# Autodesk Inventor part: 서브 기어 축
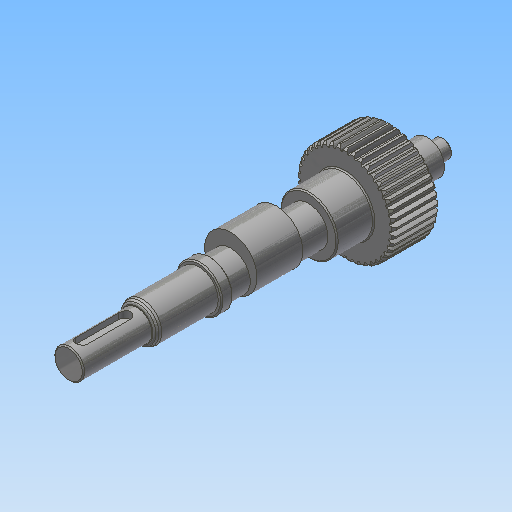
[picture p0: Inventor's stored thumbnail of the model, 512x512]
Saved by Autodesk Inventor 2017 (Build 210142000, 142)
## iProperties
Created: 2018-12
Part Number: 서브 기어 축
Material: 강철, 연강
Document SubType Name: Modeling
Designer: mduedu
Categories: <?xml version="1.0" encoding="UTF-16"?> <MemberInstance><Categories><FamilyTemplate><FamilyTemplateParameter ValueType="xs:double" Id="1" ObjectReferenceKey="da
Density: 7.86 g/cm^3
Appearance: 강철
Mass: 488.187 g
Surface Area: 153.344 cm^2
Volume: 62.1103 cm^3
Author: mduedu
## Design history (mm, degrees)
sketch "Sketch1"
  geometry: C1 r 21.3 at (0, 0)
  constraints: 1 centre point
  dimensions: "d0" = 42.6 diameter of C1 (= da_da)
extrude "Extrusion1" new body sketch "Sketch1" distance "d1" = 20 (= da_b); taper "d2" = 0 deg
workplane "Work Plane2"
sketch "Sketch2"
  geometry: C1 r 21.3 at (0, 0) reference; C2 r 20.5 at (0, 0)
  constraints: 1 centre point, 1 coincident
  dimensions: "d3" = 41 diameter of C2 (= da_dw)
feature "피치 지름" sketch "Sketch2" dims "d4" = 10, "d5" = 0
workplane "Work Plane8"
workplane "Work Plane9"
chamfer "모따기1" distance "d49" = 1; stored, may be unused: second distance "d50" = 2, angle "d51" = 45 deg
sketch "스케치3"
  geometry: C1 r 12.5 at (0, 0); 1 further point
  constraints: 1 centre point, 1 coincident
  dimensions: "d52" = 25 diameter of C1
extrude "돌출2" join sketch "스케치3" distance "d53" = 16; taper "d54" = 0 deg
sketch "스케치4"
  geometry: C1 r 8.5 at (0, 0); 1 further point
  constraints: 1 centre point, 1 coincident
  dimensions: "d55" = 17 diameter of C1
extrude "돌출3" join sketch "스케치4" distance "d56" = 105; taper "d57" = 0 deg
sketch "스케치5"
  geometry: C1 r 7.5 at (0, 0); 1 further point
  constraints: 1 centre point, 1 coincident
  dimensions: "d58" = 15 diameter of C1
extrude "돌출4" join sketch "스케치5" distance "d59" = 16; taper "d60" = 0 deg
sketch "스케치6"
  geometry: C1 r 4 at (0, 0); 1 further point
  constraints: 1 centre point, 1 coincident
  dimensions: "d61" = 8 diameter of C1
extrude "돌출5" join sketch "스케치6" distance "d62" = 7; taper "d63" = 0 deg
fillet "모깎기1" dims "d67" = 0.5
feature "스퍼 기어" dims "da_b" = 20, "da_d" = 41, "da_aw" = 31, "da_da" = 42.6, "da_df" = 39.086, "da_dw" = 41, angle "da_beta" = 0 deg, "da_lefttooth" = 0, "da_righttooth" = 0
node "작업 평면11"
sketch "스케치7"
  geometry: C1 r 11.5 at (0, 3); C2 r 8.5 at (0, 0) reference; 1 further point
  constraints: 1 centre point, 1 tangent, 1 vertical alignment
  dimensions: "d69" = 3 distance of point (0, 0) C1.centre; "d70" = 23 diameter of C1 (derived)
extrude "돌출6" join sketch "스케치7" stored distance "d71" = 20; taper "d72" = 0 deg
node "작업 평면12"
sketch "스케치8"
  geometry: C1 r 12.5 at (0, 0) reference; C2 r 10 at (0, 0); 1 further point
  constraints: 1 centre point, 1 coincident
  dimensions: "d110" = 20 diameter of C2
extrude "돌출7" join sketch "스케치8" distance "d74" = 5; taper "d75" = 0 deg
sketch "스케치14"
  geometry: L1 (-11.5, 111)-(-6.5, 111); L2 (-6.5, 111)-(-6.5, 141); L3 (-6.5, 141)-(-11.5, 141); L4 (-11.5, 141)-(-11.5, 111); L5 (8.5, 141)-(-8.5, 141) reference; L6 (0, 0)-(0, 141)
  constraints: 10 end point, 2 parallel, 1 collinear, 1 horizontal, 1 midpoint, 1 perpendicular
  dimensions: "d92" = 30 distance between parallel lines of L1 L5; "d93" = 13 diameter of L2 L6; "d95" = 5 distance of L2.end L3.end
revolve "회전2" sketch "스케치14" stored, may be unused: angle "d96" = 90 deg
chamfer "모따기4" distance "d97" = 0.5; stored, may be unused: second distance "d98" = 2, angle "d99" = 45 deg
revolve "회전1" stored, may be unused: angle "d82" = 90 deg
sketch "스케치10"
  geometry: L1 (-6.5, 117.5)-(-5, 116) reference; L2 (-6.5, 114.5)-(-5, 116) reference; 2 further points
  constraints: 1 coincident
node "작업점1"
node "작업 평면13"
sketch "스케치11"
  geometry: L1 (-2.5, 9.5)-(-2.5, -9.5); L2 (2.5, -9.5)-(2.5, 9.5); L3 (-6, 15)-(6, 15) reference; A1 r 2.5 centre (0, 9.5) between (2.5, 9.5) and (-2.5, 9.5); A2 r 2.5 centre (0, -9.5) between (-2.5, -9.5) and (2.5, -9.5); 1 further point
  constraints: 4 end point, 4 point on circle, 4 tangent, 2 centre point, 2 vertical alignment, 1 parallel
  dimensions: "d84" = 24 dimension on A2 A1; "d85" = 5 distance between parallel lines of L1 L2; "d108" = 3 distance edge to line of A1 L3
extrude "돌출8" cut sketch "스케치11" distance "d86" = 3; taper "d87" = 0 deg
sketch "스케치12" dims "d88" = 32
  geometry: C1 r 0.5 at (0, -16); 2 further points
  constraints: 2 vertical alignment, 1 centre point, 1 coincident, 2 other
  dimensions: "d89" = 1 diameter of C1
extrude "돌출9" join sketch "스케치12" distance "d90" = 0.3; taper "d91" = 0 deg
sketch "스케치13"
  geometry: C1 r 11.5 at (0, 3) reference; 1 further point
  node "절단 모서리 투영1"
sketch "스케치15"
  geometry: L1 (-8.5, 109.181)-(-7.45, 111); L2 (-8.5, 111)-(8.5, 111) reference; L3 (-8.5, 84)-(-8.5, 111) reference; L4 (0, 0)-(0, 111); L5 (-7.45, 111)-(-8.5, 111); L6 (-8.5, 109.181)-(-8.5, 111)
  constraints: 8 end point, 2 collinear, 2 point on line, 1 midpoint
  dimensions: "d103" = 14.9 diameter of L1.end L4; "d104" = 30 deg angle of L3 L1
revolve "회전3" sketch "스케치15" stored, may be unused: angle "d105" = 90 deg
fillet "모깎기2" dims "d106" = 2
fillet "모깎기3" dims "d107" = 1
chamfer "모따기5" distance "d112" = 0.5; stored, may be unused: second distance "d113" = 2, angle "d114" = 45 deg
body "Solid1"
body "Srf1"
node "투영된 루프1"
sketch "스케치9"
  geometry: L1 (0, 138.97)-(0, 0); L2 (-6.5, 116)-(0, 116); L3 (-6.5, 116)-(-6.5, 114.5); L4 (-6.5, 114.5)-(-5, 116); L5 (-5, 116)-(-6.5, 116); L6 (-6, 141)-(6, 141) reference
  constraints: 10 end point, 2 point on line, 1 collinear, 1 vertical
  dimensions: "d80" = 3 diameter of L3.end L2; "d100" = 25 distance between parallel lines of L6 L2; "d101" = 6.5 distance between parallel lines of L1 L3; "d102" = 45 deg angle of L4 L3
other parameters: "d16" = 31 (= da_aw), "d17" = 0, "d34" = 0.76624 (computed from da_z), "d39" = 0, "d41" = 0, "d43" = 31 (= da_aw), "d46" = 31 (= da_aw), "d47" = 0, "d48" = 0
